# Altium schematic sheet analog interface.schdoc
size 296 x 120 mm
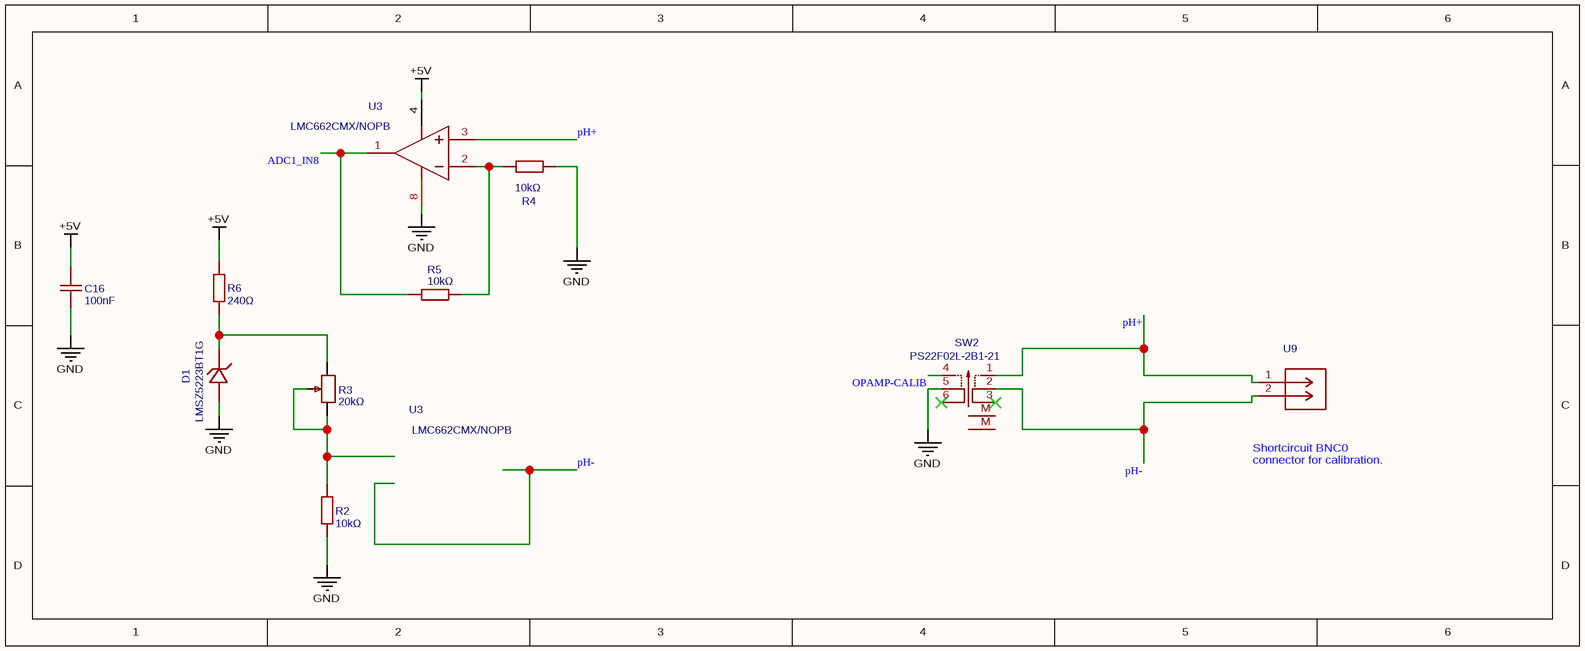
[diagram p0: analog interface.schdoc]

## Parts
(Parts that share a designator on the sheet are numbered #1, #2 ... from top to bottom, then left to right.)
C16  100nF  [C1206]
D1  LMSZ5223BT1G  [SOD-123_L2.7-W1.6-LS3.7-RD]
R2  10kΩ  [R0603]
R3  20kΩ  [RES-ADJ-TH_3362X]
R4  10kΩ  [R0603]
R5  10kΩ  [R0603]
R6  240Ω  [R0603]
SW2  PS22F02L-2B1-21  [SW-TH_6P_PS22F02L-2B1-21]
U3#1  LMC662CMX/NOPB  [SOIC-8_L5.0-W4.0-P1.27-LS6.1-BL]
U3#2  LMC662CMX/NOPB  [SOIC-8_L5.0-W4.0-P1.27-LS6.1-BL]
U9  NO  [CONN_CONBN_LNX]  (value not drawn)

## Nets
+5V: C16.2 R6.2 U3#1.4(V-)
GND: C16.1 D1.2(A) R2.1 R4.1 SW2.5 U3#1.8(V+)
ADC1_IN8: R5.2 U3#1.1(OUTA)
OPAMP-CALIB: SW2.4
pH+: SW2.1 U3#1.3(INA+) U9.1
pH-: SW2.2 U9.2
NetD1_1: D1.1(C) R3.1 R6.1
NetR2_2: R2.2 R3.2 R3.3
NetR4_2: R4.2 R5.1 U3#1.2(INA-)

Not connected (* = marked no-connect by the designer): SW2 3* 6* M

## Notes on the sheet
- (near U9) Shortcircuit BNC0
  connector for calibration.

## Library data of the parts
C16 = 100nF: Manufacturer Part: CL31B104KBCNNNC; Manufacturer: SAMSUNG(三星); nameAlias: Value
D1 = LMSZ5223BT1G: Manufacturer: LRC(乐山无线电); Contributor: LCSC
R2 R4 R5 = 10kΩ: Manufacturer: RESI(开步睿思）; Manufacturer Part: PTFR0603B10K0P9; nameAlias: Value; Contributor: LCSC
R3 = 20kΩ: Manufacturer: BOURNS; Manufacturer Part: 3362X-1-203LF; nameAlias: Value; Resistance(Ohms): 20K
R6 = 240Ω: Manufacturer: RESI(开步睿思）; Manufacturer Part: PTFR0603B240RP9; nameAlias: Value; Contributor: LCSC
SW2 = PS22F02L-2B1-21: Manufacturer: GANGYUAN(港源); Contributor: LCSC
U3#1 U3#2 = LMC662CMX/NOPB: subpart_no: 1; Manufacturer: TI(德州仪器)
U9 = NO: Contributor: rikvalentini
